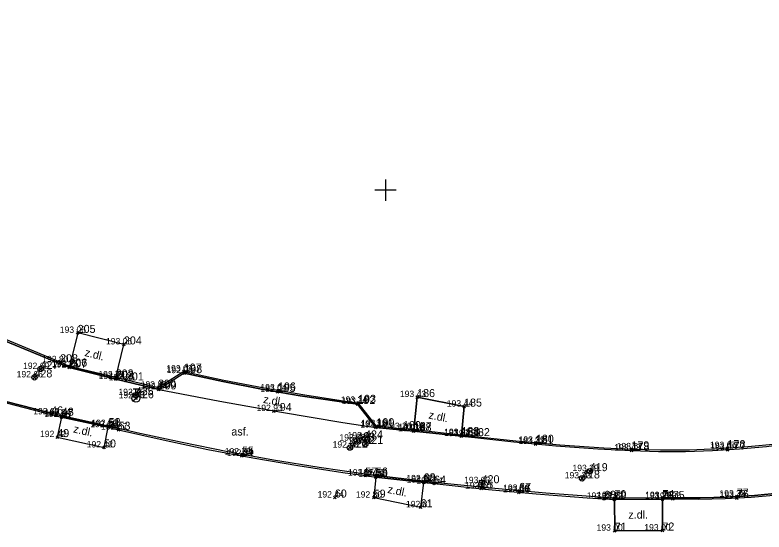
# Model space of a CAD drawing. Extents: x -706861 to -706379, y -1036456 to -1036201.
# Drawn here: x -706534.7 to -706464.5, y -1036382 to -1036333.6 of the extents above; entities that cross this region are included whole.
import ezdxf

# ---------------------------------------------------------------- set-up
doc = ezdxf.new("R2010")
doc.units = 0
for name, color, linetype in [('18_popisy', 7, 'Continuous'), ('29_vodovod', 7, 'Continuous'), ('30_kanalizace splašková', 7, 'Continuous'), ('40_plochy', 7, 'Continuous'), ('51_body polohopisu_značky', 7, 'Continuous'), ('52_body polohopisu_čísla', 7, 'Continuous'), ('53_body polohopisu_výšky', 7, 'Continuous'), ('54_body polohopisu_čísla nadbytečné pro kreslení', 7, 'Continuous'), ('5_rozhraní ploch', 7, 'Continuous'), ('60_mapový rám_legenda', 7, 'Continuous')]:
    doc.layers.add(name, color=color, linetype=linetype)

msp = doc.modelspace()

# ---------------------------------------------------------------- linework, layer by layer
at = {"layer": '29_vodovod'}
for p, q in [((-706523.64, -1036368.625), (-706523.14, -1036368.625)), ((-706523.39, -1036369.125), (-706523.39, -1036368.625)), ((-706523.684, -1036369.731), (-706523.094, -1036369.268))]:
    msp.add_line(p, q, dxfattribs=at)
for centre, radius in [((-706532.33, -1036366.76), 0.25), ((-706523.39, -1036369.5), 0.375), ((-706523.41, -1036369.21), 0.25), ((-706502.68, -1036373.47), 0.25), ((-706501.92, -1036373.26), 0.25), ((-706480.86, -1036376.33), 0.25)]:
    msp.add_circle(centre, radius, dxfattribs=at)
at = {"layer": '30_kanalizace splašková'}
msp.add_line((-706490.982, -1036377.211), (-706491.018, -1036377.709), dxfattribs=at)
msp.add_lwpolyline([(-706491.232, -1036377.192), (-706491.269, -1036377.692), (-706490.768, -1036377.728), (-706490.732, -1036377.229)], close=True, dxfattribs=at)
for centre in [(-706532.9, -1036367.55), (-706501.89, -1036373.77), (-706503.34, -1036374.12), (-706481.59, -1036377.01)]:
    msp.add_circle(centre, 0.25, dxfattribs=at)
at = {"layer": '40_plochy'}
for points in [[(-706538.88, -1036362.81), (-706529.64, -1036366.62), (-706525.27, -1036367.7), (-706521.26, -1036368.67), (-706515.52, -1036369.78), (-706509.76, -1036370.81), (-706504, -1036371.76), (-706500.92, -1036372.24), (-706497.37, -1036372.59), (-706492.9, -1036373.05), (-706491.91, -1036373.16), (-706487.98, -1036373.59), (-706484.04, -1036373.95), (-706480.1, -1036374.23), (-706476.95, -1036374.4), (-706474.42, -1036374.48), (-706471.88, -1036374.49), (-706469.35, -1036374.41), (-706466.82, -1036374.25), (-706464.3, -1036374.01)], [(-706462.89, -1036378.36), (-706465.43, -1036378.6), (-706467.98, -1036378.76), (-706470.53, -1036378.83), (-706473.08, -1036378.83), (-706474.06, -1036378.84), (-706478.55, -1036378.86), (-706479.52, -1036378.81), (-706484.99, -1036378.4), (-706490.46, -1036377.9), (-706495.45, -1036377.38), (-706496.43, -1036377.28), (-706500.9, -1036376.74), (-706501.9, -1036376.61), (-706506.21, -1036375.99), (-706510.51, -1036375.29), (-706514.79, -1036374.52), (-706519.06, -1036373.66), (-706523.32, -1036372.73), (-706524.99, -1036372.34), (-706525.95, -1036372.11), (-706530.33, -1036371.14), (-706555.02, -1036364.83)]]:
    msp.add_lwpolyline(points, dxfattribs=at)
for points in [[(-706528.85, -1036363.38), (-706529.63, -1036366.53), (-706525.29, -1036367.55), (-706524.52, -1036364.46)], [(-706500.92, -1036372.24), (-706502.63, -1036370.04), (-706504.36, -1036369.81), (-706508.01, -1036369.26), (-706511.64, -1036368.64), (-706515.26, -1036367.93), (-706518.86, -1036367.15), (-706521.26, -1036368.67), (-706515.52, -1036369.78), (-706509.76, -1036370.81), (-706504, -1036371.76)], [(-706497.35, -1036372.47), (-706497.04, -1036369.39), (-706492.64, -1036370.28), (-706492.89, -1036372.95)], [(-706530.37, -1036371.26), (-706530.76, -1036373.14), (-706526.38, -1036374.11), (-706525.98, -1036372.21)], [(-706500.92, -1036376.88), (-706501.11, -1036378.81), (-706496.7, -1036379.71), (-706496.41, -1036377.4)], [(-706474.06, -1036378.94), (-706474.06, -1036381.89), (-706478.53, -1036381.91), (-706478.56, -1036378.98)]]:
    msp.add_lwpolyline(points, close=True, dxfattribs=at)
at = {"layer": '51_body polohopisu_značky'}
for points in [[(-706528.97, -1036363.5), (-706528.73, -1036363.26)], [(-706528.97, -1036363.26), (-706528.73, -1036363.5)], [(-706524.64, -1036364.58), (-706524.4, -1036364.34)], [(-706524.64, -1036364.34), (-706524.4, -1036364.58)], [(-706530.62, -1036366.25), (-706530.38, -1036366.01)], [(-706530.62, -1036366.01), (-706530.38, -1036366.25)], [(-706529.76, -1036366.74), (-706529.52, -1036366.5)], [(-706529.76, -1036366.5), (-706529.52, -1036366.74)], [(-706529.75, -1036366.65), (-706529.51, -1036366.41)], [(-706529.75, -1036366.41), (-706529.51, -1036366.65)], [(-706532.45, -1036366.88), (-706532.21, -1036366.64)], [(-706532.45, -1036366.64), (-706532.21, -1036366.88)], [(-706519.02, -1036367.12), (-706518.78, -1036366.88)], [(-706519.02, -1036366.88), (-706518.78, -1036367.12)], [(-706518.98, -1036367.27), (-706518.74, -1036367.03)], [(-706518.98, -1036367.03), (-706518.74, -1036367.27)], [(-706533.02, -1036367.67), (-706532.78, -1036367.43)], [(-706533.02, -1036367.43), (-706532.78, -1036367.67)], [(-706525.41, -1036367.67), (-706525.17, -1036367.43)], [(-706525.41, -1036367.43), (-706525.17, -1036367.67)], [(-706525.39, -1036367.82), (-706525.15, -1036367.58)], [(-706525.39, -1036367.58), (-706525.15, -1036367.82)], [(-706524.45, -1036367.95), (-706524.21, -1036367.71)], [(-706524.45, -1036367.71), (-706524.21, -1036367.95)], [(-706521.44, -1036368.63), (-706521.2, -1036368.39)], [(-706521.44, -1036368.39), (-706521.2, -1036368.63)], [(-706521.38, -1036368.79), (-706521.14, -1036368.55)], [(-706521.38, -1036368.55), (-706521.14, -1036368.79)], [(-706510.2, -1036368.89), (-706509.96, -1036368.65)], [(-706510.2, -1036368.65), (-706509.96, -1036368.89)], [(-706523.53, -1036369.33), (-706523.29, -1036369.09)], [(-706523.53, -1036369.09), (-706523.29, -1036369.33)], [(-706510.23, -1036369.03), (-706509.99, -1036368.79)], [(-706510.23, -1036368.79), (-706509.99, -1036369.03)], [(-706497.16, -1036369.51), (-706496.92, -1036369.27)], [(-706497.16, -1036369.27), (-706496.92, -1036369.51)], [(-706523.51, -1036369.62), (-706523.27, -1036369.38)], [(-706523.51, -1036369.38), (-706523.27, -1036369.62)], [(-706502.75, -1036370.16), (-706502.51, -1036369.92)], [(-706502.75, -1036369.92), (-706502.51, -1036370.16)], [(-706502.69, -1036370.05), (-706502.45, -1036369.81)], [(-706502.69, -1036369.81), (-706502.45, -1036370.05)], [(-706510.59, -1036370.82), (-706510.35, -1036370.58)], [(-706510.59, -1036370.58), (-706510.35, -1036370.82)], [(-706492.76, -1036370.4), (-706492.52, -1036370.16)], [(-706492.76, -1036370.16), (-706492.52, -1036370.4)], [(-706531.45, -1036371.13), (-706531.21, -1036370.89)], [(-706531.45, -1036370.89), (-706531.21, -1036371.13)], [(-706530.49, -1036371.38), (-706530.25, -1036371.14)], [(-706530.49, -1036371.14), (-706530.25, -1036371.38)], [(-706530.45, -1036371.26), (-706530.21, -1036371.02)], [(-706530.45, -1036371.02), (-706530.21, -1036371.26)], [(-706526.1, -1036372.33), (-706525.86, -1036372.09)], [(-706526.1, -1036372.09), (-706525.86, -1036372.33)], [(-706526.07, -1036372.23), (-706525.83, -1036371.99)], [(-706526.07, -1036371.99), (-706525.83, -1036372.23)], [(-706501.04, -1036372.36), (-706500.8, -1036372.12)], [(-706501.04, -1036372.12), (-706500.8, -1036372.36)], [(-706500.97, -1036372.24), (-706500.73, -1036372)], [(-706500.97, -1036372), (-706500.73, -1036372.24)], [(-706525.14, -1036372.57), (-706524.9, -1036372.33)], [(-706525.14, -1036372.33), (-706524.9, -1036372.57)], [(-706498.47, -1036372.51), (-706498.23, -1036372.27)], [(-706498.47, -1036372.27), (-706498.23, -1036372.51)], [(-706497.49, -1036372.71), (-706497.25, -1036372.47)], [(-706497.49, -1036372.47), (-706497.25, -1036372.71)], [(-706497.47, -1036372.59), (-706497.23, -1036372.35)], [(-706497.47, -1036372.35), (-706497.23, -1036372.59)], [(-706493.01, -1036373.07), (-706492.77, -1036372.83)], [(-706493.01, -1036372.83), (-706492.77, -1036373.07)], [(-706530.88, -1036373.26), (-706530.64, -1036373.02)], [(-706530.88, -1036373.02), (-706530.64, -1036373.26)], [(-706502.8, -1036373.59), (-706502.56, -1036373.35)], [(-706502.8, -1036373.35), (-706502.56, -1036373.59)], [(-706502.04, -1036373.38), (-706501.8, -1036373.14)], [(-706502.04, -1036373.14), (-706501.8, -1036373.38)], [(-706493.02, -1036373.17), (-706492.78, -1036372.93)], [(-706493.02, -1036372.93), (-706492.78, -1036373.17)], [(-706492.02, -1036373.17), (-706491.78, -1036372.93)], [(-706492.02, -1036372.93), (-706491.78, -1036373.17)], [(-706486.03, -1036373.79), (-706485.79, -1036373.55)], [(-706486.03, -1036373.55), (-706485.79, -1036373.79)], [(-706526.5, -1036374.23), (-706526.26, -1036373.99)], [(-706526.5, -1036373.99), (-706526.26, -1036374.23)], [(-706503.46, -1036374.24), (-706503.22, -1036374)], [(-706503.46, -1036374), (-706503.22, -1036374.24)], [(-706502.01, -1036373.89), (-706501.77, -1036373.65)], [(-706502.01, -1036373.65), (-706501.77, -1036373.89)], [(-706486.07, -1036373.91), (-706485.83, -1036373.67)], [(-706486.07, -1036373.67), (-706485.83, -1036373.91)], [(-706477.08, -1036374.4), (-706476.84, -1036374.16)], [(-706477.08, -1036374.16), (-706476.84, -1036374.4)], [(-706468.09, -1036374.29), (-706467.85, -1036374.05)], [(-706468.09, -1036374.05), (-706467.85, -1036374.29)], [(-706468.06, -1036374.45), (-706467.82, -1036374.21)], [(-706468.06, -1036374.21), (-706467.82, -1036374.45)], [(-706513.59, -1036375.02), (-706513.35, -1036374.78)], [(-706513.59, -1036374.78), (-706513.35, -1036375.02)], [(-706513.57, -1036374.89), (-706513.33, -1036374.65)], [(-706513.57, -1036374.65), (-706513.33, -1036374.89)], [(-706477.07, -1036374.52), (-706476.83, -1036374.28)], [(-706477.07, -1036374.28), (-706476.83, -1036374.52)], [(-706480.98, -1036376.45), (-706480.74, -1036376.21)], [(-706480.98, -1036376.21), (-706480.74, -1036376.45)], [(-706502.02, -1036376.86), (-706501.78, -1036376.62)], [(-706502.02, -1036376.62), (-706501.78, -1036376.86)], [(-706501.04, -1036377), (-706500.8, -1036376.76)], [(-706501.04, -1036376.76), (-706500.8, -1036377)], [(-706501.02, -1036376.86), (-706500.78, -1036376.62)], [(-706501.02, -1036376.62), (-706500.78, -1036376.86)], [(-706481.71, -1036377.13), (-706481.47, -1036376.89)], [(-706481.71, -1036376.89), (-706481.47, -1036377.13)], [(-706496.55, -1036377.4), (-706496.31, -1036377.16)], [(-706496.55, -1036377.16), (-706496.31, -1036377.4)], [(-706496.53, -1036377.52), (-706496.29, -1036377.28)], [(-706496.53, -1036377.28), (-706496.29, -1036377.52)], [(-706495.58, -1036377.62), (-706495.34, -1036377.38)], [(-706495.58, -1036377.38), (-706495.34, -1036377.62)], [(-706491.12, -1036377.58), (-706490.88, -1036377.34)], [(-706491.12, -1036377.34), (-706490.88, -1036377.58)], [(-706491.16, -1036378.08), (-706490.92, -1036377.84)], [(-706491.16, -1036377.84), (-706490.92, -1036378.08)], [(-706487.63, -1036378.44), (-706487.39, -1036378.2)], [(-706487.63, -1036378.2), (-706487.39, -1036378.44)], [(-706487.6, -1036378.3), (-706487.36, -1036378.06)], [(-706487.6, -1036378.06), (-706487.36, -1036378.3)], [(-706504.87, -1036378.92), (-706504.63, -1036378.68)], [(-706504.87, -1036378.68), (-706504.63, -1036378.92)], [(-706501.23, -1036378.93), (-706500.99, -1036378.69)], [(-706501.23, -1036378.69), (-706500.99, -1036378.93)], [(-706479.65, -1036379.04), (-706479.41, -1036378.8)], [(-706479.65, -1036378.8), (-706479.41, -1036379.04)], [(-706478.68, -1036379.1), (-706478.44, -1036378.86)], [(-706478.68, -1036378.86), (-706478.44, -1036379.1)], [(-706478.67, -1036378.98), (-706478.43, -1036378.74)], [(-706478.67, -1036378.74), (-706478.43, -1036378.98)], [(-706474.18, -1036379.06), (-706473.94, -1036378.82)], [(-706474.18, -1036378.82), (-706473.94, -1036379.06)], [(-706474.17, -1036378.97), (-706473.93, -1036378.73)], [(-706474.17, -1036378.73), (-706473.93, -1036378.97)], [(-706473.21, -1036379.05), (-706472.97, -1036378.81)], [(-706473.21, -1036378.81), (-706472.97, -1036379.05)], [(-706467.21, -1036378.83), (-706466.97, -1036378.59)], [(-706467.21, -1036378.59), (-706466.97, -1036378.83)], [(-706467.2, -1036378.97), (-706466.96, -1036378.73)], [(-706467.2, -1036378.73), (-706466.96, -1036378.97)], [(-706496.83, -1036379.83), (-706496.59, -1036379.59)], [(-706496.83, -1036379.59), (-706496.59, -1036379.83)], [(-706478.65, -1036382.03), (-706478.41, -1036381.79)], [(-706478.65, -1036381.79), (-706478.41, -1036382.03)], [(-706474.18, -1036382.01), (-706473.94, -1036381.77)], [(-706474.18, -1036381.77), (-706473.94, -1036382.01)]]:
    msp.add_lwpolyline(points, dxfattribs=at)
at = {"layer": '5_rozhraní ploch'}
for points in [[(-706670.86, -1036333.6), (-706654.96, -1036337.67), (-706645.7, -1036340.05), (-706641.34, -1036341.16), (-706626.555, -1036344.932), (-706621.962, -1036346.105), (-706617.12, -1036347.34), (-706609.33, -1036349.34), (-706607.89, -1036351.73), (-706591.92, -1036355.83), (-706589.44, -1036354.45), (-706583.46, -1036355.97), (-706564.29, -1036360.86), (-706559.11, -1036363.05), (-706555.02, -1036364.83), (-706530.33, -1036371.14), (-706525.95, -1036372.11), (-706524.99, -1036372.34)], [(-706518.9, -1036367), (-706521.32, -1036368.51), (-706525.29, -1036367.55), (-706529.63, -1036366.53), (-706530.5, -1036366.13), (-706538.84, -1036362.64), (-706552.4, -1036359.15), (-706553.35, -1036358.9), (-706557.68, -1036357.75), (-706581.42, -1036351.68), (-706582.39, -1036351.45), (-706586.73, -1036350.34), (-706587.71, -1036350.1), (-706610.95, -1036344.11), (-706611.94, -1036343.85), (-706616.28, -1036342.77), (-706617.25, -1036342.5), (-706639.52, -1036336.83)], [(-706518.86, -1036367.15), (-706521.26, -1036368.67), (-706525.27, -1036367.7), (-706529.64, -1036366.62), (-706538.88, -1036362.81), (-706553.4, -1036359.02), (-706557.72, -1036357.91), (-706582.43, -1036351.58), (-706586.78, -1036350.45), (-706610.97, -1036344.21), (-706611.97, -1036343.95)], [(-706525.29, -1036367.55), (-706524.52, -1036364.46), (-706528.85, -1036363.38), (-706529.63, -1036366.53)], [(-706518.9, -1036367), (-706515.14, -1036367.81), (-706511.36, -1036368.54), (-706507.56, -1036369.19), (-706503.76, -1036369.77), (-706502.57, -1036369.93)], [(-706518.86, -1036367.15), (-706515.26, -1036367.93), (-706511.64, -1036368.64), (-706508.01, -1036369.26), (-706504.36, -1036369.81), (-706502.63, -1036370.04)], [(-706538.83, -1036369.1), (-706531.32, -1036371.01), (-706530.37, -1036371.26), (-706525.98, -1036372.21), (-706525.02, -1036372.45)], [(-706521.26, -1036368.67), (-706515.52, -1036369.78), (-706509.76, -1036370.81), (-706504, -1036371.76), (-706500.92, -1036372.24)], [(-706491.91, -1036373.16), (-706492.9, -1036373.05), (-706497.37, -1036372.59), (-706500.92, -1036372.24), (-706502.63, -1036370.04)], [(-706491.9, -1036373.05), (-706492.89, -1036372.95), (-706497.35, -1036372.47), (-706498.35, -1036372.39), (-706500.85, -1036372.12), (-706502.57, -1036369.93)], [(-706492.89, -1036372.95), (-706492.64, -1036370.28), (-706497.04, -1036369.39), (-706497.35, -1036372.47)], [(-706530.37, -1036371.26), (-706530.76, -1036373.14), (-706526.38, -1036374.11), (-706525.98, -1036372.21)], [(-706525.02, -1036372.45), (-706520.85, -1036373.41), (-706516.65, -1036374.29), (-706512.45, -1036375.09), (-706508.23, -1036375.81), (-706503.99, -1036376.45), (-706501.9, -1036376.74)], [(-706501.9, -1036376.61), (-706506.21, -1036375.99), (-706510.51, -1036375.29), (-706514.79, -1036374.52), (-706519.06, -1036373.66), (-706523.32, -1036372.73), (-706524.99, -1036372.34)], [(-706491.91, -1036373.16), (-706487.98, -1036373.59), (-706484.04, -1036373.95), (-706480.1, -1036374.23), (-706476.95, -1036374.4)], [(-706491.9, -1036373.05), (-706487.79, -1036373.49), (-706483.67, -1036373.86), (-706479.55, -1036374.14), (-706476.96, -1036374.28)], [(-706476.96, -1036374.28), (-706474.23, -1036374.34), (-706471.51, -1036374.32), (-706468.78, -1036374.22), (-706466.06, -1036374.03), (-706463.35, -1036373.77), (-706461.97, -1036373.61)], [(-706476.95, -1036374.4), (-706474.42, -1036374.48), (-706471.88, -1036374.49), (-706469.35, -1036374.41), (-706466.82, -1036374.25), (-706464.3, -1036374.01), (-706461.95, -1036373.72)], [(-706501.9, -1036376.61), (-706500.9, -1036376.74), (-706496.43, -1036377.28), (-706495.45, -1036377.38)], [(-706501.9, -1036376.74), (-706500.92, -1036376.88), (-706496.41, -1036377.4), (-706495.46, -1036377.5)], [(-706500.92, -1036376.88), (-706501.11, -1036378.81), (-706496.7, -1036379.71), (-706496.41, -1036377.4)], [(-706495.46, -1036377.5), (-706490.69, -1036378.02), (-706485.9, -1036378.46), (-706481.11, -1036378.82), (-706479.53, -1036378.92)], [(-706479.52, -1036378.81), (-706484.99, -1036378.4), (-706490.46, -1036377.9), (-706495.45, -1036377.38)], [(-706473.08, -1036378.83), (-706470.53, -1036378.83), (-706467.98, -1036378.76), (-706465.43, -1036378.6), (-706462.89, -1036378.36), (-706460.35, -1036378.04), (-706460.11, -1036378.01)], [(-706473.08, -1036378.93), (-706470.63, -1036378.96), (-706468.18, -1036378.9), (-706465.73, -1036378.77), (-706463.29, -1036378.55), (-706460.85, -1036378.26), (-706460.1, -1036378.15)], [(-706479.53, -1036378.92), (-706478.56, -1036378.98), (-706474.06, -1036378.94), (-706473.08, -1036378.93)], [(-706479.52, -1036378.81), (-706478.55, -1036378.86), (-706474.06, -1036378.84)], [(-706478.56, -1036378.98), (-706478.53, -1036381.91), (-706474.06, -1036381.89), (-706474.06, -1036378.94)], [(-706474.06, -1036378.84), (-706473.08, -1036378.83)]]:
    msp.add_lwpolyline(points, dxfattribs=at)
at = {"layer": '60_mapový rám_legenda'}
for points in [[(-706500, -1036349), (-706500, -1036350), (-706500, -1036351)], [(-706499, -1036350), (-706500, -1036350), (-706501, -1036350)]]:
    msp.add_lwpolyline(points, dxfattribs=at)

# ---------------------------------------------------------------- texts
at = {"layer": '18_popisy'}
for rotation, p in [(345.9949, (-706528.246, -1036365.532)), (350.29335, (-706511.498, -1036369.93)), (348.56491, (-706496.015, -1036371.393)), (347.51275, (-706529.306, -1036372.696)), (348.46538, (-706499.864, -1036378.359)), (0.25636, (-706477.246, -1036380.782))]:
    msp.add_text('z.dl.', height=0.75, rotation=rotation, dxfattribs=at).set_placement(p)
msp.add_text('asf.', height=0.75, dxfattribs=at).set_placement((-706514.45, -1036372.99))
at = {"layer": '52_body polohopisu_čísla'}
for s, p in [('205', (-706528.85, -1036363.38)), ('204', (-706524.52, -1036364.46)), ('206', (-706529.63, -1036366.53)), ('427', (-706532.33, -1036366.76)), ('198', (-706518.86, -1036367.15)), ('202', (-706525.29, -1036367.55)), ('199', (-706521.26, -1036368.67)), ('425', (-706523.41, -1036369.21)), ('195', (-706510.11, -1036368.91)), ('186', (-706497.04, -1036369.39)), ('193', (-706502.57, -1036369.93)), ('185', (-706492.64, -1036370.28)), ('46', (-706531.33, -1036371.01)), ('190', (-706500.85, -1036372.12)), ('53', (-706525.02, -1036372.45)), ('189', (-706498.35, -1036372.39)), ('49', (-706530.76, -1036373.14)), ('184', (-706492.9, -1036373.05)), ('50', (-706526.38, -1036374.11)), ('422', (-706503.34, -1036374.12)), ('180', (-706485.91, -1036373.67)), ('54', (-706513.47, -1036374.9)), ('178', (-706476.95, -1036374.4)), ('177', (-706467.94, -1036374.33)), ('57', (-706501.9, -1036376.74)), ('418', (-706481.59, -1036377.01)), ('62', (-706496.41, -1036377.4)), ('65', (-706491.04, -1036377.96)), ('66', (-706487.51, -1036378.32)), ('60', (-706504.75, -1036378.8)), ('73', (-706474.06, -1036378.94)), ('77', (-706467.09, -1036378.71)), ('61', (-706496.71, -1036379.71)), ('71', (-706478.53, -1036381.91)), ('72', (-706474.06, -1036381.89))]:
    msp.add_text(s, height=0.75, dxfattribs=at).set_placement(p)
at = {"layer": '53_body polohopisu_výšky'}
for s, p in [('193 06 ', (-706530.527, -1036363.38)), ('193 06 ', (-706526.197, -1036364.46)), ('192 80 ', (-706532.17, -1036366.13)), ('192 69 ', (-706533.969, -1036366.76)), ('192 74 ', (-706531.258, -1036366.62)), ('192 75 ', (-706531.248, -1036366.53)), ('193 03 ', (-706520.544, -1036367)), ('192 96 ', (-706520.513, -1036367.15)), ('192 66 ', (-706534.568, -1036367.55)), ('192 79 ', (-706526.913, -1036367.55)), ('192 78 ', (-706526.888, -1036367.7)), ('192 85 ', (-706525.948, -1036367.83)), ('192 89 ', (-706522.943, -1036368.51)), ('192 75 ', (-706525.028, -1036369.21)), ('192 84 ', (-706522.878, -1036368.67)), ('192 97 ', (-706511.73, -1036368.91)), ('193 04 ', (-706511.724, -1036368.77)), ('192 73 ', (-706525.008, -1036369.5)), ('193 24 ', (-706504.188, -1036369.93)), ('193 43 ', (-706498.658, -1036369.39)), ('193 16 ', (-706504.111, -1036370.04)), ('193 44 ', (-706494.258, -1036370.28)), ('192 60 ', (-706533.016, -1036371.01)), ('192 55 ', (-706531.988, -1036371.26)), ('192 54 ', (-706531.948, -1036371.14)), ('192 93 ', (-706512.09, -1036370.7)), ('192 60 ', (-706527.666, -1036372.21)), ('192 59 ', (-706527.573, -1036372.11)), ('192 67 ', (-706526.655, -1036372.45)), ('193 14 ', (-706502.368, -1036372.24)), ('193 18 ', (-706502.298, -1036372.12)), ('193 20 ', (-706500.02, -1036372.39)), ('193 15 ', (-706498.818, -1036372.59)), ('193 17 ', (-706498.798, -1036372.47)), ('192 42 ', (-706532.378, -1036373.14)), ('193 02 ', (-706504.324, -1036373.47)), ('193 04 ', (-706503.564, -1036373.26)), ('193 22 ', (-706494.518, -1036373.05)), ('193 23 ', (-706494.508, -1036372.95)), ('193 30 ', (-706493.57, -1036373.05)), ('192 42 ', (-706527.998, -1036374.11)), ('192 98 ', (-706504.96, -1036374.12)), ('193 02 ', (-706503.534, -1036373.77)), ('193 32 ', (-706487.568, -1036373.79)), ('193 39 ', (-706487.533, -1036373.67)), ('193 67 ', (-706469.605, -1036374.17)), ('192 73 ', (-706515.068, -1036374.77)), ('193 43 ', (-706478.568, -1036374.4)), ('193 51 ', (-706478.337, -1036374.28)), ('193 59 ', (-706469.563, -1036374.33)), ('192 81 ', (-706514.847, -1036374.9)), ('192 95 ', (-706503.52, -1036376.74)), ('192 92 ', (-706502.54, -1036376.88)), ('192 92 ', (-706502.52, -1036376.74)), ('193 29 ', (-706482.483, -1036376.33)), ('192 97 ', (-706498.05, -1036377.28)), ('192 97 ', (-706498.03, -1036377.4)), ('193 04 ', (-706497.104, -1036377.5)), ('193 03 ', (-706492.644, -1036377.46)), ('193 23 ', (-706483.208, -1036377.01)), ('193 10 ', (-706492.54, -1036377.96)), ('193 16 ', (-706488.991, -1036378.32)), ('193 10 ', (-706488.98, -1036378.18)), ('192 44 ', (-706506.368, -1036378.8)), ('192 80 ', (-706502.78, -1036378.81)), ('193 27 ', (-706481.148, -1036378.92)), ('193 23 ', (-706480.178, -1036378.98)), ('193 22 ', (-706480.168, -1036378.86)), ('193 29 ', (-706475.683, -1036378.94)), ('193 29 ', (-706475.673, -1036378.85)), ('193 36 ', (-706474.741, -1036378.93)), ('193 38 ', (-706468.708, -1036378.71)), ('193 44 ', (-706468.698, -1036378.85)), ('192 81 ', (-706498.087, -1036379.71)), ('193 00 ', (-706475.756, -1036381.89)), ('193 00 ', (-706480.226, -1036381.91))]:
    msp.add_text(s, height=0.6, dxfattribs=at).set_placement(p)
at = {"layer": '54_body polohopisu_čísla nadbytečné pro kreslení'}
for s, p in [('208', (-706530.5, -1036366.13)), ('207', (-706529.64, -1036366.62)), ('197', (-706518.9, -1036367)), ('428', (-706532.9, -1036367.55)), ('203', (-706525.27, -1036367.7)), ('201', (-706524.33, -1036367.83)), ('200', (-706521.32, -1036368.51)), ('196', (-706510.08, -1036368.77)), ('426', (-706523.39, -1036369.5)), ('192', (-706502.63, -1036370.04)), ('194', (-706510.47, -1036370.7)), ('47', (-706530.37, -1036371.26)), ('48', (-706530.33, -1036371.14)), ('51', (-706525.98, -1036372.21)), ('52', (-706525.95, -1036372.11)), ('191', (-706500.92, -1036372.24)), ('188', (-706497.37, -1036372.59)), ('187', (-706497.35, -1036372.47)), ('423', (-706502.68, -1036373.47)), ('424', (-706501.92, -1036373.26)), ('183', (-706492.89, -1036372.95)), ('182', (-706491.9, -1036373.05)), ('421', (-706501.89, -1036373.77)), ('181', (-706485.95, -1036373.79)), ('179', (-706476.96, -1036374.28)), ('176', (-706467.97, -1036374.17)), ('55', (-706513.45, -1036374.77)), ('419', (-706480.86, -1036376.33)), ('58', (-706500.92, -1036376.88)), ('56', (-706500.9, -1036376.74)), ('63', (-706496.43, -1036377.28)), ('64', (-706495.46, -1036377.5)), ('420', (-706491, -1036377.46)), ('67', (-706487.48, -1036378.18)), ('59', (-706501.11, -1036378.81)), ('68', (-706479.53, -1036378.92)), ('69', (-706478.56, -1036378.98)), ('70', (-706478.55, -1036378.86)), ('74', (-706474.05, -1036378.85)), ('75', (-706473.09, -1036378.93)), ('76', (-706467.08, -1036378.85))]:
    msp.add_text(s, height=0.75, dxfattribs=at).set_placement(p)

doc.saveas('drawing.dxf')
